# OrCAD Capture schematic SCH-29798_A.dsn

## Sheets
1 01 Title Page, Rev History: title: X-FRDM-HB2000ES-EVM; rev: A; company: NXP Semiconductors; note: SCH-29798 PDF: SPF-29798; note: 6501 William Cannon Drive West; note: Austin, TX 78735-8598
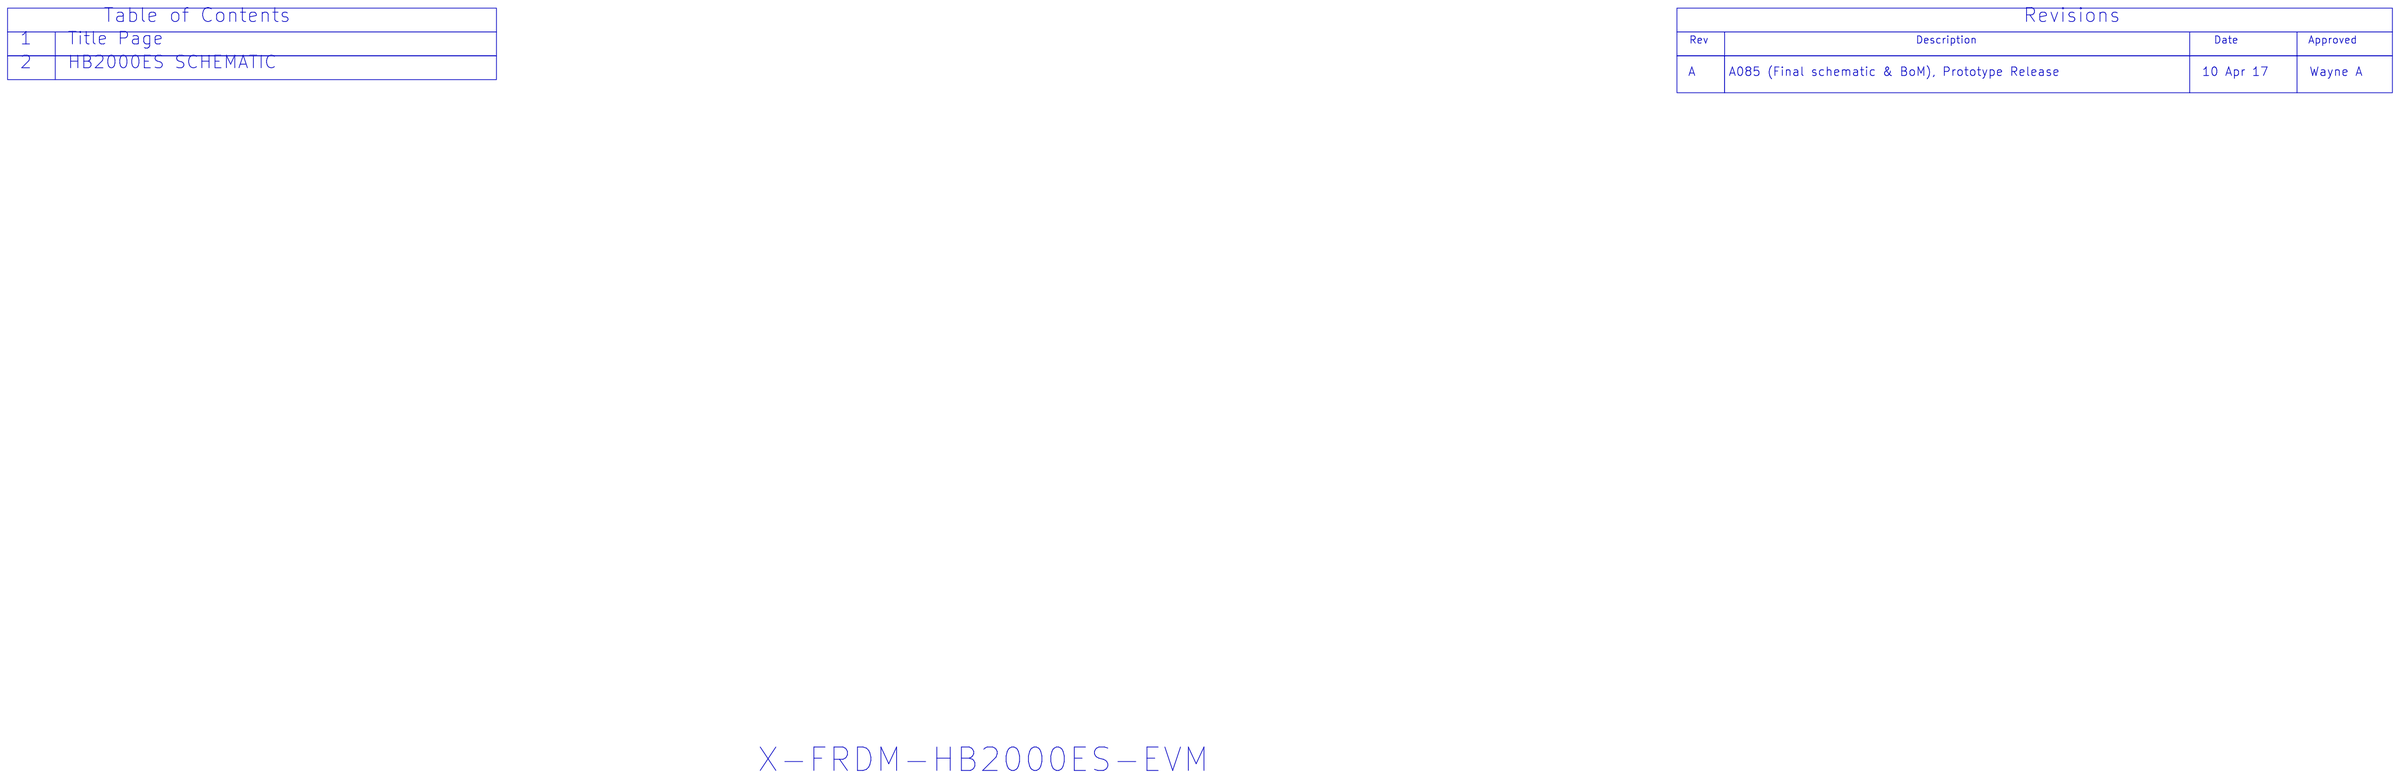
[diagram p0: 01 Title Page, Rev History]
2 02 HB2000ES: size C
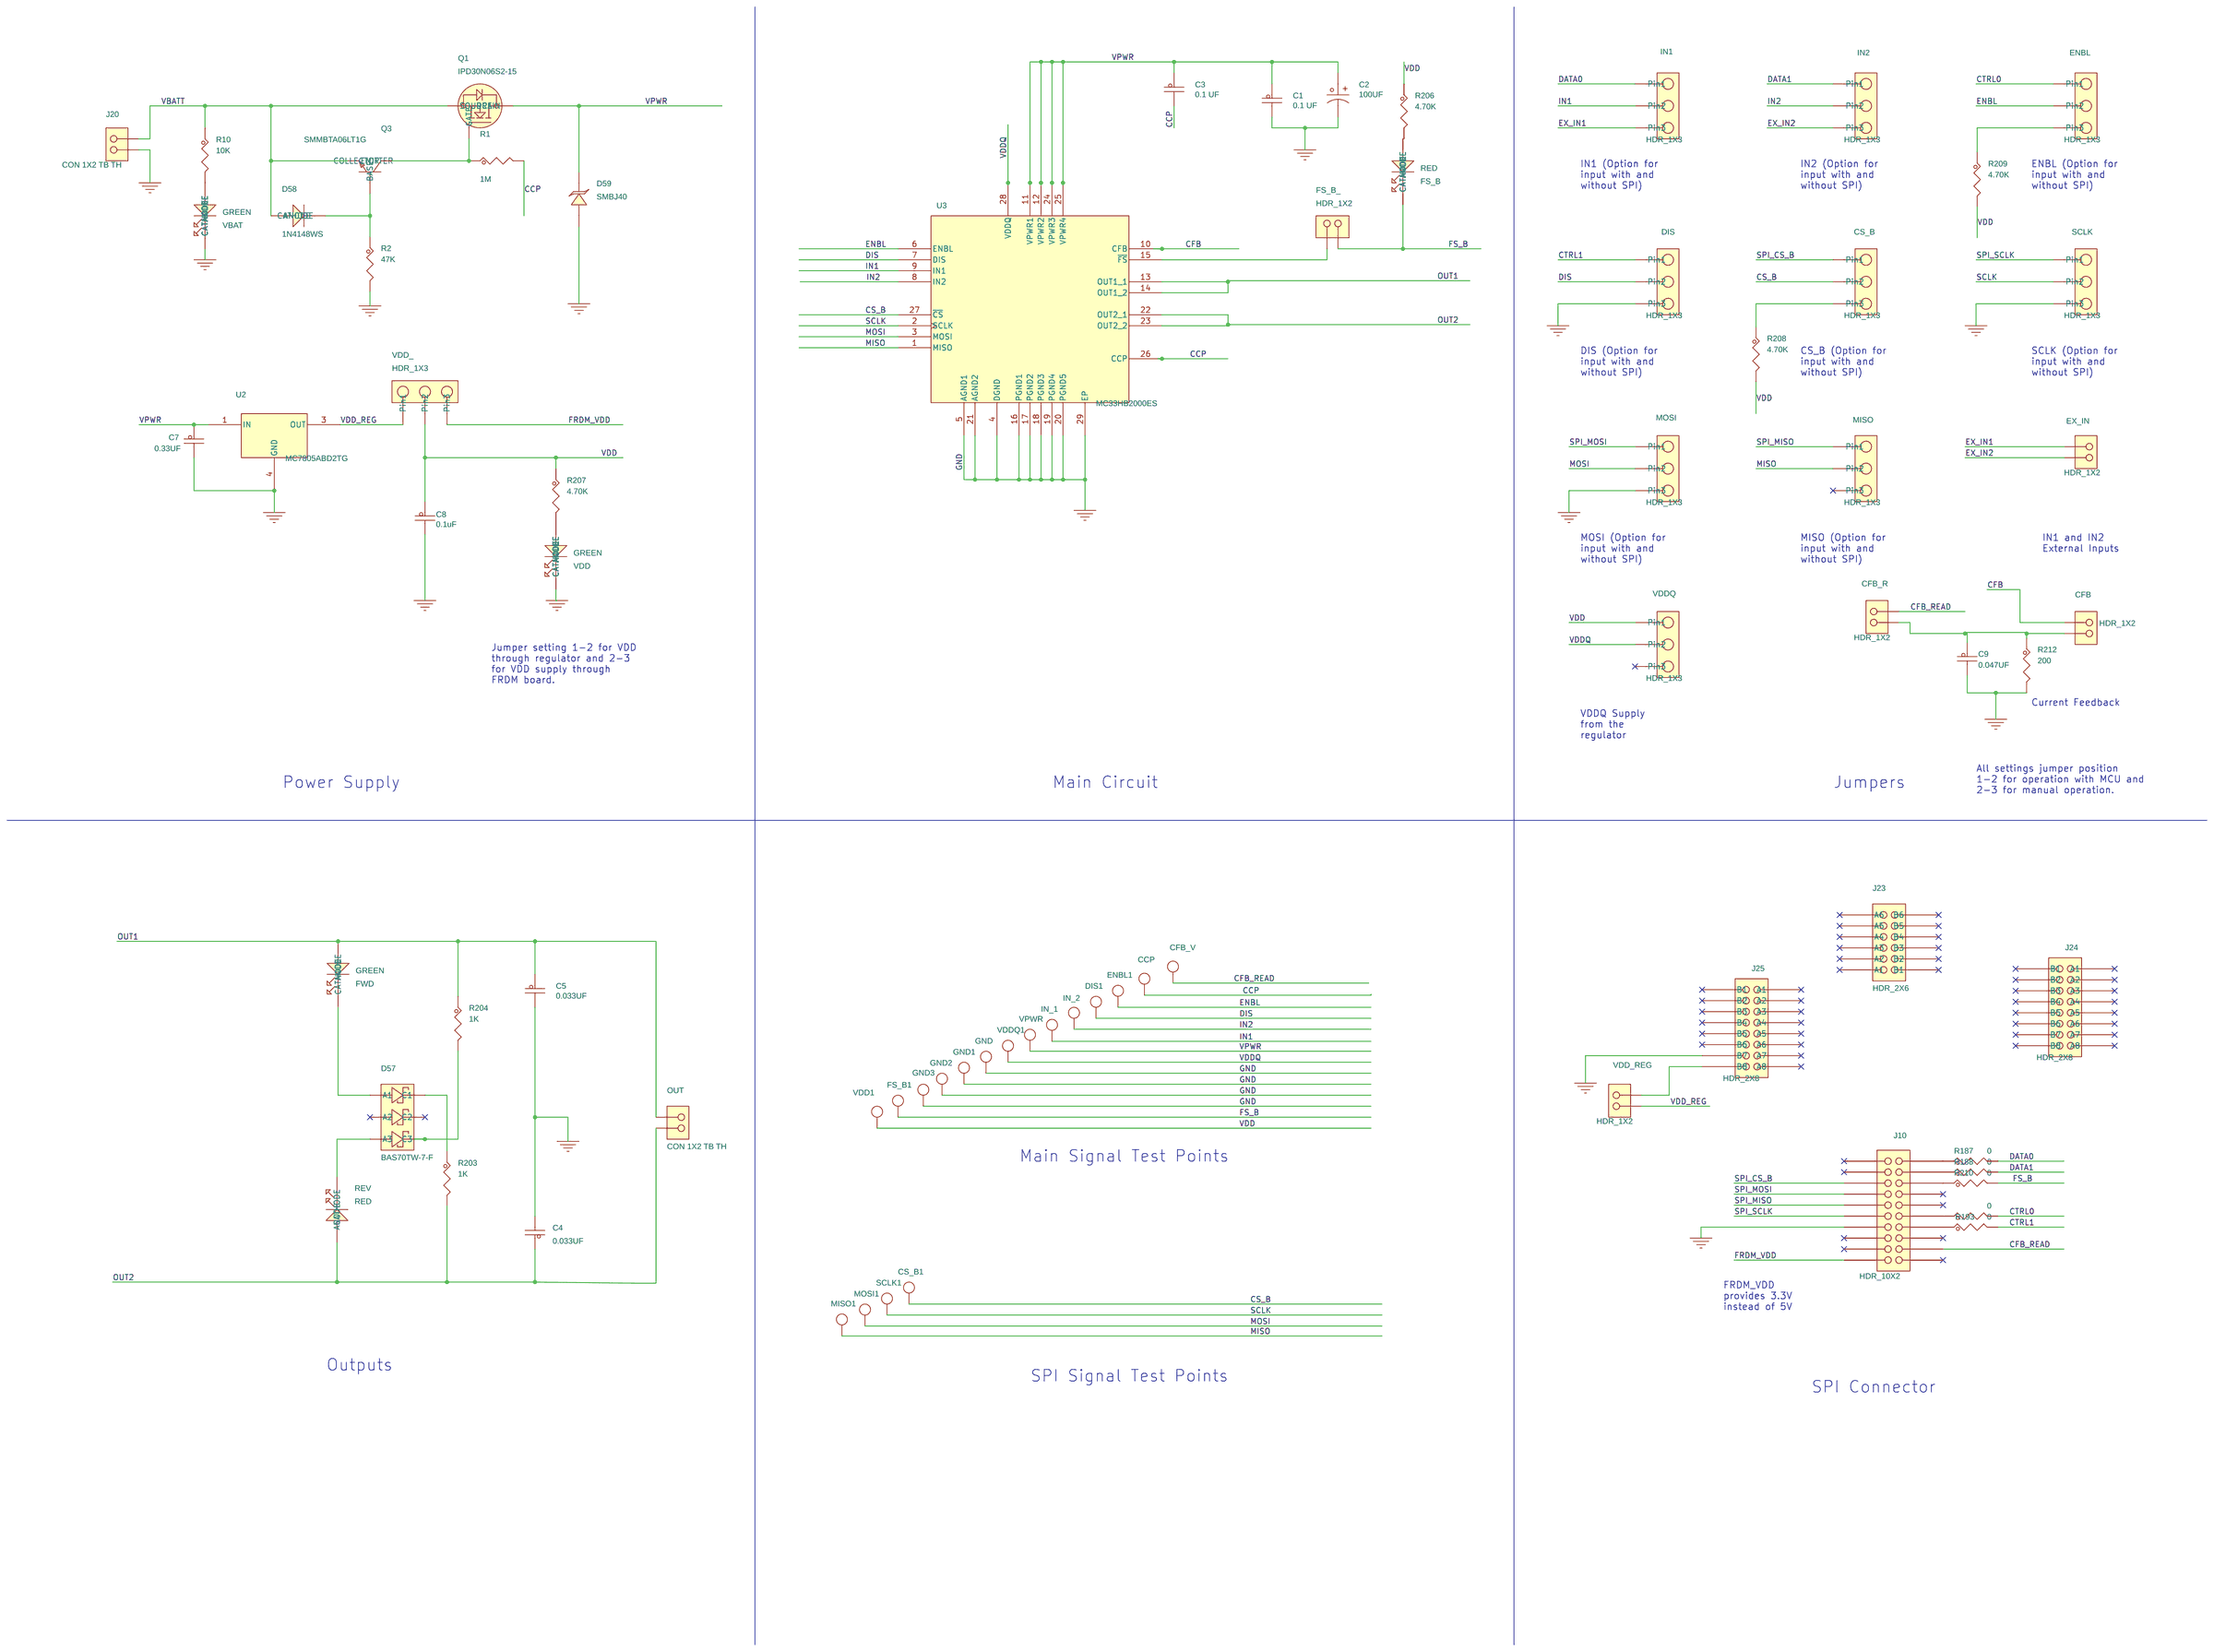
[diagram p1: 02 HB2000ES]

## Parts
C1  0.1 UF  [CC0805_OV]
C2  100UF  [cap_10dia_10p5]
C3  0.1 UF  [CC0805_OV]
C4  0.033UF  [CC0805_OV]
C5  0.033UF  [CC0805_OV]
C7  0.33UF  [CC0603_OV]
C8  0.1uF  [CC0603_OV]
C9  0.047UF  [CC0603_OV]
CCP  TEST POINT BLACK  [TEST_LOOP]
CFB  HDR_1X2  [HDR102]
CFB_R  HDR_1X2  [HDR102]
CFB_V  TEST POINT BLACK  [TEST_LOOP]
CS_B  HDR_1X3  [HDR103]
CS_B1  TEST POINT BLACK  [TEST_LOOP]
D57  BAS70TW-7-F  [sc70-6]
D58  1N4148WS  [SOD323]
D59  SMBJ40  [DO-214AA_A]
DIS  HDR_1X3  [HDR103]
DIS1  TEST POINT BLACK  [TEST_LOOP]
ENBL  HDR_1X3  [HDR103]
ENBL1  TEST POINT BLACK  [TEST_LOOP]
EX_IN  HDR_1X2  [HDR102]
FS_B  RED  [led2_2p34_2p1x1p25]
FS_B1  TEST POINT BLACK  [TEST_LOOP]
FS_B_  HDR_1X2  [HDR102]
FWD  GREEN  [led2_2p34_2p1x1p25]
GND  TEST POINT BLACK  [TEST_LOOP]
GND1  TEST POINT BLACK  [TEST_LOOP]
GND2  TEST POINT BLACK  [TEST_LOOP]
GND3  TEST POINT BLACK  [TEST_LOOP]
IN1  HDR_1X3  [HDR103]
IN2  HDR_1X3  [HDR103]
IN_1  TEST POINT BLACK  [TEST_LOOP]
IN_2  TEST POINT BLACK  [TEST_LOOP]
J10  HDR_10X2  [hdr210]
J20  CON 1X2 TB TH  [conn_2_tb_5p08_th]
J23  HDR_2X6  [HDR206]
J24  HDR_2X8  [HDR208]
J25  HDR_2X8  [HDR208]
MISO  HDR_1X3  [HDR103]
MISO1  TEST POINT BLACK  [TEST_LOOP]
MOSI  HDR_1X3  [HDR103]
MOSI1  TEST POINT BLACK  [TEST_LOOP]
OUT  CON 1X2 TB TH  [conn_2_tb_5p08_th]
Q1  IPD30N06S2-15  [to252_dpak_st]
Q3  SMMBTA06LT1G  [sot23_a]
R1  1M  [RC0603_OV]
R2  47K  [RC0603_OV]
R10  10K  [RC0603_OV]
R187  0  [RC0603_OV]
R188  0  [RC0603_OV]
R192  0  [RC0603_OV]
R193  0  [RC0603_OV]
R203  1K  [RC0603_OV]
R204  1K  [RC0603_OV]
R206  4.70K  [RC0603_OV]
R207  4.70K  [RC0603_OV]
R208  4.70K  [RC0603_OV]
R209  4.70K  [RC0603_OV]
R210  0  [RC0603_OV]
R212  200  [RC0603_OV]
REV  RED  [led2_2p34_2p1x1p25]
SCLK  HDR_1X3  [HDR103]
SCLK1  TEST POINT BLACK  [TEST_LOOP]
U2  MC7805ABD2TG  [d2pak_d2t]
U3  MC33HB2000ES  [QFN28_0P65_6X6_EP4P2]
VBAT  GREEN  [led2_2p34_2p1x1p25]
VDD  GREEN  [led2_2p34_2p1x1p25]
VDD1  TEST POINT BLACK  [TEST_LOOP]
VDD_  HDR_1X3  [HDR103]
VDD_REG  HDR_1X2  [HDR102]
VDDQ  HDR_1X3  [HDR103]
VDDQ1  TEST POINT BLACK  [TEST_LOOP]
VPWR  TEST POINT BLACK  [TEST_LOOP]

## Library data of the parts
C1 C3 = CAP_NP: CAP CER 0.1UF 50V 10% X7R 0805; AGILE_PN: 150-75018; CAD_APPROVED: Yes; FPLIST: CC0805_OV,CC0805,0805_CC; HEIGHT: 1.4732 MM; MFG_NAME01: KEMET; MFG_PN01: C0805C104K5RAC; ROHS: Yes; Tolerance: 10%; VOLTAGE: 50V
C2 = CAP_POL: CAP ALEL 100UF 50V 20% AEC-Q200 RADIAL SMT; AGILE_PN: 150-79346; CAD_APPROVED: Yes; HEIGHT: 12.5MM; MFG_NAME01: VISHAY INTERTECHNOLOGY; MFG_PN01: MAL214699104E3; ROHS: Yes
C4 C5 = CAP_NP: CAP CER 0.033UF 50V 10% X7R 0805; AGILE_PN: 150-75120; CAD_APPROVED: Yes; FPLIST: CC0805_OV,CC0805,0805_CC; HEIGHT: 1.4732 mm; MFG_NAME01: AVX; MFG_PN01: 08055C333KAT2A; ROHS: Yes; Tolerance: 10%; VOLTAGE: 50V
C7 = CAP_NP: CAP CER 0.33UF 50V 10% X7R 0603; AGILE_PN: 150-79257; CAD_APPROVED: Yes; FPLIST: CC0603_OV,CC0603,0603_CC; HEIGHT: 0.9MM; MFG_NAME01: TDK; MFG_PN01: C1608X7R1H334K080AC; ROHS: Yes; Tolerance: 10%; VOLTAGE: 50V
C8 = CAP_NP: CAP CER 0.1uF 16V 10% X7R AEC-Q200 0603; AGILE_PN: 150-79338; CAD_APPROVED: Yes; FPLIST: CC0603_OV,CC0603,0603_CC; HEIGHT: 0.9 MM; MFG_NAME01: MURATA; MFG_PN01: GCM188R71C104KA37D; ROHS: Yes; Tolerance: 10%; VOLTAGE: 16V
C9 = CAP_NP: CAP CER 0.047UF 25V 10% X7R 0603; AGILE_PN: 150-75199; CAD_APPROVED: Yes; FPLIST: CC0603_OV,CC0603,0603_CC; HEIGHT: 0.9652mm; MFG_NAME01: VENKEL COMPANY; MFG_PN01: C0603X7R250-473KNE; ROHS: Yes; Tolerance: 10%; VOLTAGE: 25V
CCP CFB_V CS_B1 DIS1 ENBL1 FS_B1 GND GND1-GND3 IN_1 IN_2 MISO1 MOSI1 SCLK1 VDD1 VDDQ1 VPWR = TestLoop: TEST POINT BLACK 40 MIL DRILL 180 MIL TH 109L; AGILE_PN: 210-75683; CAD_APPROVED: Yes; HEIGHT: 4.8mm; MFG_NAME01: KEYSTONE ELECTRONICS; MFG_PN01: 5001; ROHS: Yes
CFB CFB_R EX_IN FS_B_ VDD_REG = CONN_HDR_2X1: HDR 1X2 TH 100MIL SP 378H AU 130L; AGILE_PN: 210-75673; CAD_APPROVED: Yes; HEIGHT: 9.6 MM; MFG_NAME01: TYCO ELECTRONICS; MFG_PN01: 826629-2; ROHS: Yes
CS_B DIS ENBL IN1 IN2 MISO MOSI SCLK VDD_ VDDQ = Jumper_3Pin: HDR 1X3 TH 100MIL SP 374H AU; AGILE_PN: 210-30039; CAD_APPROVED: Yes; HEIGHT: 9.5 MM; MFG_NAME01: TYCO ELECTRONICS; MFG_PN01: 826629-3; ROHS: Yes
D57 = BAS70TW: DIODE SCH TRIPLE 70MA 70V / 200MW SOT363; AGILE_PN: 480-76817; CAD_APPROVED: Yes; HEIGHT: 1.1 MM; MFG_NAME01: DIODES INC; ROHS: Yes
D58 = DIODE: DIODE SW 150MA 75V SOD-323; AGILE_PN: 480-75133; CAD_APPROVED: Yes; HEIGHT: 1.05MM; MFG_NAME01: DIODES INC; MFG_PN01: 1N4148WS-7-F; ROHS: Yes
D59 = DIODE_TVS: DIODE TVS 9.3A 40V SMB SMT; AGILE_PN: 480-78239; CAD_APPROVED: Yes; HEIGHT: 2.62MM; MFG_NAME01: BOURNS; MFG_PN01: SMBJ40A; ROHS: Yes
FS_B REV = LED: LED RED SGL 25MA 0805; AGILE_PN: 370-76435; CAD_APPROVED: Yes; HEIGHT: 0.8MM; MFG_NAME01: Dialight; MFG_PN01: 598-8110-107F; ROHS: Yes
FWD VBAT VDD = LED: LED GRN SGL 25MA 0805; AGILE_PN: 370-76437; CAD_APPROVED: Yes; HEIGHT: 0.8MM; MFG_NAME01: Dialight; MFG_PN01: 598-8170-107F; ROHS: Yes
J10 = CONN_HDR_10X2: HDR 2X10 TH 100MIL CTR 330H AU 100L; AGILE_PN: 210-76001; CAD_APPROVED: Yes; FPLIST: hdr210,hdr210_mirror_nsp; HEIGHT: 8.71 MM; MFG_NAME01: SAMTEC; MFG_PN01: TSW-110-07-S-D; ROHS: Yes
J20 OUT = CONN_HDR_2X1: CON 1X2 TB TH 5.08MM 543H SN 138L; AGILE_PN: 210-80162; CAD_APPROVED: Yes; HEIGHT: 13.8MM; MFG_NAME01: FCI; MFG_PN01: 20020316-H021B01LF; ROHS: Yes
J23 = CONN_HDR_6X2: HDR 2X6 TH 100MIL CTR 330H AU; AGILE_PN: 210-11415-12; CAD_APPROVED: Yes; HEIGHT: 8.382 MM; MFG_NAME01: SAMTEC; MFG_PN01: TSW-106-07-S-D; ROHS: Yes
J24 J25 = CONN_HDR_8X2: HDR 2X8 TH 100MIL CTR 330H AU; AGILE_PN: 210-11112-00; CAD_APPROVED: Yes; HEIGHT: 8.58MM; MFG_NAME01: SAMTEC; MFG_PN01: TSW-108-07-G-D; ROHS: Yes
Q1 = MOSFET_N_D4: TRAN NMOS PWR 30A 55V AEC-Q101 TO252; AGILE_PN: 480-78781; CAD_APPROVED: Yes; HEIGHT: 2.35MM; MFG_NAME01: Infineon Technologies; ROHS: Yes
Q3 = NPN: TRAN NPN DRIVER 500MA 80V AEC-Q101 SOT23; AGILE_PN: 480-78787; CAD_APPROVED: Yes; HEIGHT: 1.11MM; MFG_NAME01: ON SEMICONDUCTOR; ROHS: Yes
R1 = RES: RES 1M OHM 1/4W 1% AEC-Q200 0603; AGILE_PN: 470-80822; CAD_APPROVED: Yes; FPLIST: RC0603_OV,RC0603,0603_CC; HEIGHT: 0.55MM; MFG_NAME01: VISHAY INTERTECHNOLOGY; MFG_PN01: CRCW06031M00FKEAHP; ROHS: Yes; Tolerance: 1%
R2 = RES: RES MF 47K 1/10W 1% AEC-Q200 0603; AGILE_PN: 470-80846; CAD_APPROVED: Yes; FPLIST: RC0603_OV,RC0603,0603_CC; HEIGHT: 0.5 MM; MFG_NAME01: VISHAY INTERTECHNOLOGY; MFG_PN01: CRCW060347K0FKEA; ROHS: Yes; Tolerance: 1%
R10 = RES: RES MF 10K 1/10W 5% AEC-Q200 0603; AGILE_PN: 470-80778; CAD_APPROVED: Yes; FPLIST: RC0603_OV,RC0603,0603_CC; HEIGHT: 0.55MM; MFG_NAME01: Panasonic; MFG_PN01: ERJ-3GEYJ103V; ROHS: Yes; Tolerance: 5%
R187 R188 R192 R193 R210 = RES: RES MF ZERO OHM 1/10W -- AEC-Q200 0603; AGILE_PN: 470-75407; CAD_APPROVED: Yes; FPLIST: RC0603_OV,RC0603,R603-X2,0603_CC; HEIGHT: 0.6MM; MFG_NAME01: KOA SPEER; MFG_PN01: RK73Z1JTTD; ROHS: Yes; Tolerance: 1%
R203 R204 = RES: RES MF 1K 1/10W 1% 0603; AGILE_PN: 470-80784; CAD_APPROVED: Yes; FPLIST: RC0603_OV,RC0603,0603_CC; HEIGHT: 0.55MM; MFG_NAME01: VIKING TECH CORPORATION; MFG_PN01: AR03FTNX1001; ROHS: Yes; Tolerance: 1%
R206-R209 = RES: RES MF 4.70K 1/10W 1% 0603; AGILE_PN: 470-75430; CAD_APPROVED: Yes; FPLIST: RC0603_OV,RC0603,0603_CC; HEIGHT: 0.55 MM; MFG_NAME01: BOURNS; MFG_PN01: CR0603-FX-4701ELF; ROHS: Yes; Tolerance: 1%
R212 = RES: RES MF 200 OHM 1/10W 1% 0603; AGILE_PN: 470-30029; CAD_APPROVED: Yes; FPLIST: RC0603_OV,RC0603,0603_CC; HEIGHT: 0.6 MM; MFG_NAME01: BOURNS; MFG_PN01: CR0603-FX-2000ELF; ROHS: Yes; Tolerance: 1%
U2 = MC7805: IC VREG 5V 1A 5-18V D2PAK; AGILE_PN: 315-79847; CAD_APPROVED: Yes; HEIGHT: 4.572MM; MFG_NAME01: ON Semiconductor; ROHS: Yes
U3 = MC33HB2000EP_QFN_28P: IC H-BRIDGE SPI BRUSHED DC MOTOR DRIVER 10A 5-28V QFN28; AGILE_PN: TMP-WF-29532; CAD_APPROVED: Yes; HEIGHT: 1 MM; MFG_NAME01: NXP SEMICONDUCTORS; PRE_APN: 315-81339; ROHS: Yes

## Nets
GND: C1.2 C2.2 C4.2 C5.2 C7.2 C8.2 C9.2 D59.A DIS.3(Pin3) GND.1(Pin1) GND1.1(Pin1) GND2.1(Pin1) GND3.1(Pin1) J10.14 J20.2 J25.14(B7) MOSI.3(Pin3) R2.2 R212.2 SCLK.3(Pin3) U2.4(GND) U3.4(DGND) U3.5(AGND1) U3.16(PGND1) U3.17(PGND2) U3.18(PGND3) U3.19(PGND4) U3.20(PGND5) U3.21(AGND2) U3.29(EP) VBAT.C(CATHODE) VDD.C(CATHODE)
VBATT: D58.A(ANODE) J20.1 Q1.3(SOURCE) Q3.2(EMITTER) R10.1
VDD: C8.1 R206.1 R207.1 R208.2 R209.2 VDD1.1(Pin1) VDD_.2(Pin2) VDDQ.1(Pin1)
VDD_REG: U2.3(OUT) VDD_.1(Pin1) VDD_REG.2
VDDQ: U3.28(VDDQ) VDDQ.2(Pin2) VDDQ1.1(Pin1)
CCP: C3.2 CCP.1(Pin1) R1.2 U3.26(CCP)
CFB: CFB.1 U3.10(CFB)
CFB_READ: CFB_R.1 CFB_V.1(Pin1) J10.17
CS_B: CS_B.2(Pin2) CS_B1.1(Pin1) U3.27(~{CS})
CTRL0: ENBL.1(Pin1) R192.2
CTRL1: DIS.1(Pin1) R193.2
DATA0: IN1.1(Pin1) R187.2
DATA1: IN2.1(Pin1) R188.2
DIS: DIS.2(Pin2) DIS1.1(Pin1) U3.7(DIS)
ENBL: ENBL.2(Pin2) ENBL1.1(Pin1) U3.6(ENBL)
EX_IN1: EX_IN.1 IN1.3(Pin3)
EX_IN2: EX_IN.2 IN2.3(Pin3)
FRDM_VDD: J10.20 VDD_.3(Pin3)
FS_B: FS_B.C(CATHODE) FS_B1.1(Pin1) FS_B_.2 R210.2
IN1: IN1.2(Pin2) IN_1.1(Pin1) U3.9(IN1)
IN2: IN2.2(Pin2) IN_2.1(Pin1) U3.8(IN2)
MISO: MISO.2(Pin2) MISO1.1(Pin1) U3.1(MISO)
MOSI: MOSI.2(Pin2) MOSI1.1(Pin1) U3.3(MOSI)
OUT1: C5.1 FWD.A(ANODE) OUT.1 R204.1 U3.13(OUT1_1) U3.14(OUT1_2)
OUT2: C4.1 OUT.2 R203.2 REV.A(ANODE) U3.22(OUT2_1) U3.23(OUT2_2)
SCLK: SCLK.2(Pin2) SCLK1.1(Pin1) U3.2(SCLK)
SPI_CS_B: CS_B.1(Pin1) J10.6
SPI_MISO: J10.10 MISO.1(Pin1)
SPI_MOSI: J10.8 MOSI.1(Pin1)
SPI_SCLK: J10.12 SCLK.1(Pin1)
VPWR: C1.1 C2.1 C3.1 C7.1 D59.C Q1.4(DRAIN) U2.1(IN) U3.11(VPWR1) U3.12(VPWR2) U3.24(VPWR3) U3.25(VPWR4) VPWR.1(Pin1)
N15086994: Q1.1(GATE) Q3.3(COLLECTOR) R1.1
N15515059: ENBL.3(Pin3) R209.1
N15516808: CS_B.3(Pin3) R208.1
N15517603: C9.1 CFB.2 CFB_R.2 R212.1
N15519474: D57.1(A1) FWD.C(CATHODE)
N15519750: D57.3(A3) REV.C(CATHODE)
N15519985: D57.6(C1) R203.1
N15520366: D57.4(C3) R204.2
N15536961: D58.C(CATHODE) Q3.1(BASE) R2.1
N15544276: FS_B_.1 U3.15(~{FS})
N15562112: FS_B.A(ANODE) R206.2
N15568529: J25.16(B8) VDD_REG.1
N16504197: J10.5 R210.1
N16504199: J10.3 R188.1
N16504200: J10.1 R187.1
N16504201: J10.11 R192.1
N16504203: J10.13 R193.1
N16506529: R10.2 VBAT.A(ANODE)
N16506530: R207.2 VDD.A(ANODE)

Not connected (* = marked no-connect by the designer): D57 2(A2)* 5(C2)*; J10 2* 4* 7* 9* 15* 16* 18* 19*; J23 1(A1)* 2(B1)* 3(A2)* 4(B2)* 5(A3)* 6(B3)* 7(A4)* 8(B4)* 9(A5)* 10(B5)* 11(A6)* 12(B6)*; J24 1(A1)* 2(B1)* 3(A2)* 4(B2)* 5(A3)* 6(B3)* 7(A4)* 8(B4)* 9(A5)* 10(B5)* 11(A6)* 12(B6)* 13(A7)* 14(B7)* 15(A8)* 16(B8)*; J25 1(A1)* 2(B1)* 3(A2)* 4(B2)* 5(A3)* 6(B3)* 7(A4)* 8(B4)* 9(A5)* 10(B5)* 11(A6)* 12(B6)* 13(A7)* 15(A8)*; MISO 3(Pin3)*; VDDQ 3(Pin3)*

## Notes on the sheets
sheet 1
- Table of Contents
- Revisions
- 1
- Title Page
- Rev
- Description
- Date
- Approved
- 2
- HB2000ES SCHEMATIC
- A
- A085 (Final schematic & BoM), Prototype Release
- 10 Apr 17
- Wayne A
- X-FRDM-HB2000ES-EVM
sheet 2
- IN1 (Option for
  input with and
  without SPI)
- IN2 (Option for
  input with and
  without SPI)
- ENBL (Option for
  input with and
  without SPI)
- DIS (Option for
  input with and
  without SPI)
- CS_B (Option for
  input with and
  without SPI)
- SCLK (Option for
  input with and
  without SPI)
- MOSI (Option for
  input with and
  without SPI)
- MISO (Option for
  input with and
  without SPI)
- IN1 and IN2
  External Inputs
- Jumper setting 1-2 for VDD
  through regulator and 2-3
  for VDD supply through
  FRDM board.
- Current Feedback
- VDDQ Supply
  from the
  regulator
- Power Supply
- Main Circuit
- Jumpers
- All settings jumper position
  1-2 for operation with MCU and
  2-3 for manual operation.
- Main Signal Test Points
- FRDM_VDD
  provides 3.3V
  instead of 5V
- Outputs
- SPI Signal Test Points
- SPI Connector
